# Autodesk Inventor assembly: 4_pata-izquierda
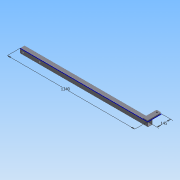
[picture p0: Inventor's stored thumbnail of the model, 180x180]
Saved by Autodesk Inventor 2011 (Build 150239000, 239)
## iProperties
Created: 2020-12
Part Number: 4_pata-izquierda
Document SubType Name: Assembly
Designer: PC
Mass: 8098.06 g
Surface Area: 4945.21 cm^2
Volume: 1030.29 cm^3
Density: 7.86 g/cm^3
_SolveAssemblyDoc: Frame Generator Solve Assembly
_Version: 15.0.0
Author: PC
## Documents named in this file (3)
- C:\Users\PC\Documents\Inventor\workshop-crane-powered-by-drill\4_pata-izquierda.iam
- C:\Users\PC\Documents\Inventor\workshop-crane-powered-by-drill\4_pata-izquierda_esqueleto.ipt
- C:\Users\PC\Documents\Inventor\workshop-crane-powered-by-drill\4_pata-izquierda\Frame\Frame0001.iam
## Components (2 placed, 2 different names)
1. 4_pata-izquierda_esqueleto:1
2. Frame0001:1 [sub-assembly]
